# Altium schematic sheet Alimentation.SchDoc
size Letter; Organization: Cegep Limoilou; Address1: 1300, 8e Avenue; Address2: Québec, QC; Address3: Canada; Address4: G1J 5L5; Revision: Enseignants; SheetNumber: 5; SheetTotal: 8; Conception: Ilyes Gharmoul; Titre: Alimentation; Modification: Ilyes G
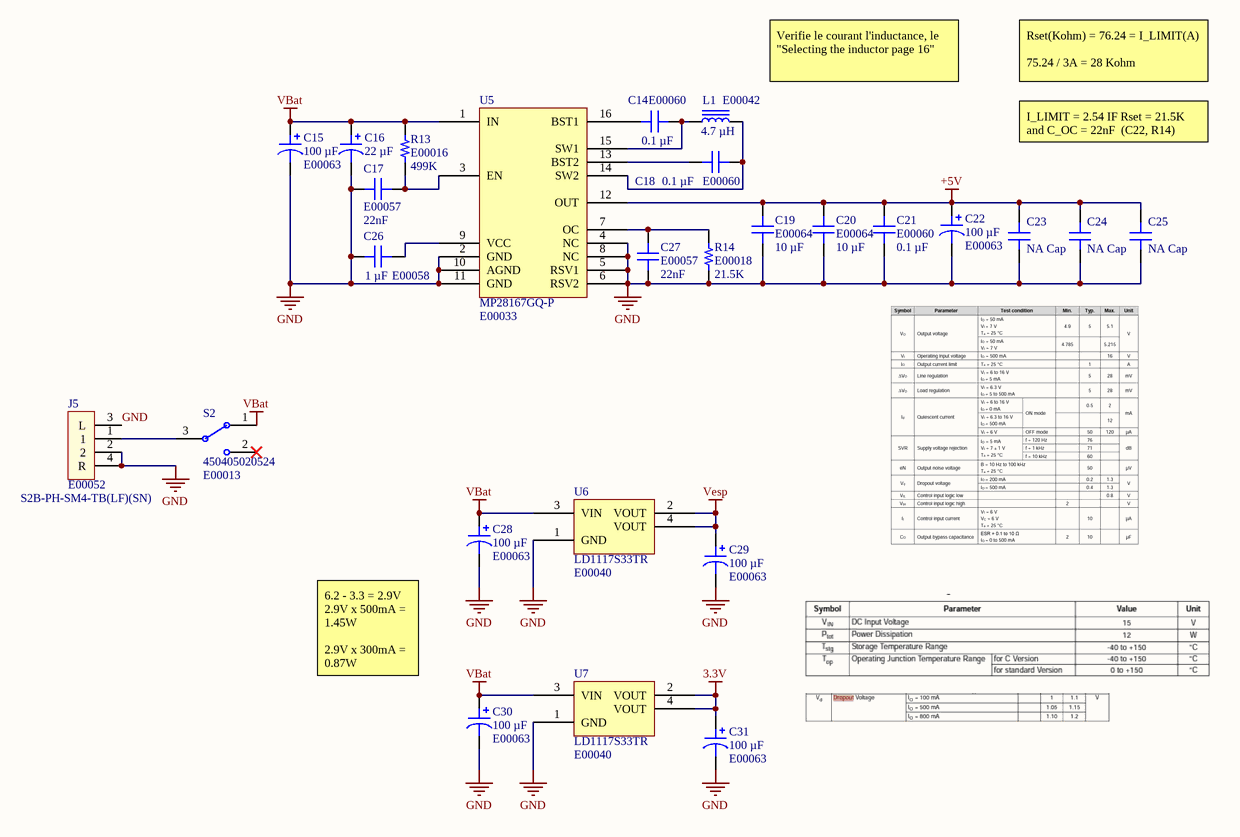
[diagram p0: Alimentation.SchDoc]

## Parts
C14  ADAM Inventory Number 1: E00060  [CAP 0603]  (hidden comment: 0.1 µF)
C15  100 µF  ADAM Inventory Number 1: E00063  [CAP ALSMD ELEC 8.3MM H10.5MM]
C16  22 µF  [CAP ALSMD 4.3MM H5.4MM]
C17  ADAM Inventory Number 1: E00057  [CAP 0603]  (hidden comment: 22nF)
C18  ADAM Inventory Number 1: E00060  [CAP 0603]  (hidden comment: 0.1 µF)
C19  ADAM Inventory Number 1: E00064  [CAP 0603]  (hidden comment: 10 µF)
C20  ADAM Inventory Number 1: E00064  [CAP 0603]  (hidden comment: 10 µF)
C21  ADAM Inventory Number 1: E00060  [CAP 0603]  (hidden comment: 0.1 µF)
C22  100 µF  ADAM Inventory Number 1: E00063  [CAP ALSMD ELEC 8.3MM H10.5MM]
C23  NA Cap  [CAP 0603]
C24  NA Cap  [CAP 0603]
C25  NA Cap  [CAP 0603]
C26  ADAM Inventory Number 1: E00058  [CAP 0603]  (hidden comment: 1 µF)
C27  ADAM Inventory Number 1: E00057  [CAP 0603]  (hidden comment: 22nF)
C28  100 µF  ADAM Inventory Number 1: E00063  [CAP ALSMD ELEC 8.3MM H10.5MM]
C29  100 µF  ADAM Inventory Number 1: E00063  [CAP ALSMD ELEC 8.3MM H10.5MM]
C30  100 µF  ADAM Inventory Number 1: E00063  [CAP ALSMD ELEC 8.3MM H10.5MM]
C31  100 µF  ADAM Inventory Number 1: E00063  [CAP ALSMD ELEC 8.3MM H10.5MM]
J5  ADAM Inventory Number 1: E00052  Supplier Part Number 1: S2B-PH-SM4-TB(LF)(SN)  [S2B-PH-SM4-TB_LF__SN]  (hidden comment: CONN JST 2P SM 90DEG)
L1  4.7 µH  ADAM Inventory Number 1: E00042  [IND 4.7UH 4.6A]
R13  ADAM Inventory Number 1: E00016  [RES 0603]  (hidden comment: 499K)
R14  ADAM Inventory Number 1: E00018  [RES 0603]  (hidden comment: 21.5K)
S2  450405020524  ADAM Inventory Number 1: E00013  [SL 3Pos Switch]
U5  MP28167GQ-P  ADAM Inventory Number 1: E00033  [MP2816GQ-P]
U6  LD1117S33TR  ADAM Inventory Number 1: E00040  [SOT-223]
U7  LD1117S33TR  ADAM Inventory Number 1: E00040  [SOT-223]

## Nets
3.3V: C31.1 U7.2(VOUT) U7.4(VOUT)
+5V: C19.2 C20.2 C21.2 C22.1 C23.1 C24.1 C25.1 U5.12(OUT)
GND: C15.2 C16.2 C17.1 C19.1 C20.1 C21.1 C22.2 C23.2 C24.2 C25.2 C26.2 C27.1 C28.2 C29.2 C30.2 C31.2 J5.2 J5.3(L) J5.4(R) R14.1 U5.2(GND) U5.4(NC) U5.5(RSV1) U5.6(RSV2) U5.8(NC) U5.10(AGND) U5.11(GND) U6.1(GND) U7.1(GND)
VBat: C15.1 C16.1 C28.1 C30.1 R13.2 S2.1 U5.1(IN) U6.3(VIN) U7.3(VIN)
Vesp: C29.1 U6.2(VOUT) U6.4(VOUT)
NetC14_1: C14.1 L1.1 U5.15(SW1)
NetC14_2: C14.2 U5.16(BST1)
NetC17_2: C17.2 R13.1 U5.3(EN)
NetC18_1: C18.1 L1.2 U5.14(SW2)
NetC18_2: C18.2 U5.13(BST2)
NetC26_1: C26.1 U5.9(VCC)
NetC27_2: C27.2 R14.2 U5.7(OC)
NetJ5_1: J5.1 S2.3(COM)

Not connected (* = marked no-connect by the designer): S2 2*

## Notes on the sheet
- Verifie le courant l'inductance, le "Selecting the inductor page 16"
- Rset(Kohm) = 76.24 = I_LIMIT(A)
  75.24 / 3A = 28 Kohm
- I_LIMIT = 2.54 IF Rset = 21.5K and C_OC = 22nF  (C22, R14)
- 6.2 - 3.3 = 2.9V
  2.9V x 500mA =
  1.45W
  2.9V x 300mA =
  0.87W

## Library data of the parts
C14 C18 C21 = CAP CER 0.1UF 50V X7R 0603: Manufacturer Part Number 1: C0603C104K5RAC7411; manufacturer: KEMET; Tolerance: ±10%
C15 C22 C28-C31 = CAP ALUM 100UF 20% 50V SMD: Manufacturer Part Number 1: UWT1H101MNL1GS; manufacturer: Nichicon; Lifetime @ Temp.: 1000 Hrs @ 105°C; Polarization: Polar; Ripple Current @ High Frequency: 210 mA @ 10 kHz; Ripple Current @ Low Frequency: 140 mA @ 120 Hz; Surface Mount Land Size: 0.327" L x 0.327" W (8.30mm x 8.30mm)
C16 = EEE-1CA220WAR: CAP ALUM 22UF 20% 16V SMD; manufacturer: Panasonic Electronic Components; Lifetime @ Temp.: 1000 Hrs @ 85°C; Polarization: Polar; Ripple Current @ High Frequency: 47.6 mA @ 10 kHz; Ripple Current @ Low Frequency: 28 mA @ 120 Hz; Surface Mount Land Size: 0.169" L x 0.169" W (4.30mm x 4.30mm)
C17 C27 = CAP CER 22NF 15V 10% 0603: CAP CER 22pF 15V 10% 0603, X7R; manufacturer: Taiyo Yuden; Manufacturer Part Number 1: EMF107B7223KAHT; Voltage - Rated: 16V
C19 C20 = CAP 10UF 6.3V: CAP CER 10UF 6.3V X5R 0603; Manufacturer Part Number 1: GRM188R60J106ME47D; manufacturer: Murata Electronics; Tolerance: ±20%
C23-C25 = NA Cap 0603: No capacitor, just in case
C26 = CAP CER 1UF 16V X7R 0603: Manufacturer Part Number 1: C0603C105K4RACAUTO; manufacturer: KEMET; Tolerance: ±10%
J5 = CONN JST 2P SM 90DEG: CONN SM JST 2P
L1 = IND 4.7UH 4.6A: FIXED IND 4.7UH 4.6A 53 MOHM SMD; Manufacturer Part Number 1: SRP5030T-4R7M; Manufacturer: Bourns Inc.; Current - Saturation: 6A; DC Resistance (DCR): 53mOhm Max; Inductance Frequency - Test: 100 kHz; Material - Core: Iron Powder; Shielding: Shielded; Tolerance: ±20%; Type: Drum Core, Wirewound
R13 = RES SMD 499K OHM: RES SMD 499K OHM 1% 1/4W 0603; Manufacturer: Vishay Dale; Manufacturer Part Number 1: RC0603FR-07499KL; Power (Watts): 0.25W, 1/4W; Temperature Coefficient: ±100ppm/°C
R14 = RES SMD 21.5K OHM: RES SMD 21.5K OHM 0.1% 1/5W 0603; Manufacturer: Panasonic Electronic Components; Manufacturer Part Number 1: CRCW0603321K5FKEA; Power (Watts): 0.2W, 1/5W; Temperature Coefficient: ±50ppm/°C
S2 = SLIDE SWIT: SMT 8.7 X 3.0 MM MINI SLIDE SWIT; Manufacturer: Würth Elektronik; Rated Current: 300mA; Rated Voltage: 5VDC; Switching Function: On-On; Circuit: SPDT; Actuator Length: 2.00mm; Actuator Type: Standard; Contact Timing: Non-Shorting (BBM); Current Rating (Amps): 300mA (DC); Voltage Rating - DC: 5 V
U5 = MP28167GQ-P: Buck-Boost Switching Regulator IC Positive Fixed 5V 1 Output 3A 16-PowerVFQFN
U6 U7 = LD1117S33TR: IC REG LINEAR 3.3V 800MA SOT223; Manufacturer: STMicroelectronics; Current - Quiescent (Iq): 10 mA; Number of Regulators: 1; Output Configuration: Positive; Output Type: Fixed; Protection Features: Over Current, Over Temperature; PSRR: 75dB (120Hz); Voltage Dropout (Max): 1.2V @ 800mA; Voltage - Input (Max): 15V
